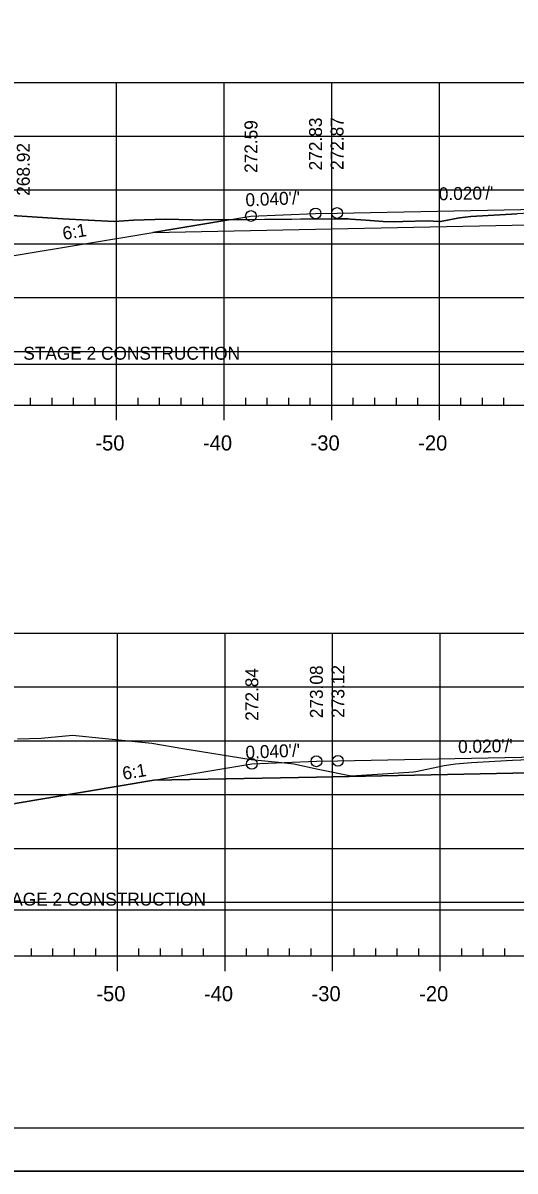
# Model space of a CAD drawing. Extents: x 1365647 to 1367999, y 387113 to 400173.
# Drawn here: x 1365836.1 to 1365881.8, y 388866.1 to 388972.8 of the extents above; entities that cross this region are included whole.
import ezdxf

# ---------------------------------------------------------------- set-up
doc = ezdxf.new("R2010")
doc.units = 0
for name, color, linetype in [('R_Alt Surface', 7, 'Continuous'), ('R_Axis', 7, 'Continuous'), ('R_Axis Annot', 7, 'Continuous'), ('R_Border', 7, 'Continuous'), ('R_Contours', 7, 'Continuous'), ('R_Exist Surface', 7, 'Continuous'), ('R_Fin Surface', 7, 'Continuous'), ('R_Fin Surface Annot', 7, 'Continuous'), ('R_Grid', 7, 'Continuous'), ('R_No Plot', 7, 'Continuous'), ('R_Water', 7, 'Continuous')]:
    doc.layers.add(name, color=color, linetype=linetype)

msp = doc.modelspace()

# ---------------------------------------------------------------- linework, layer by layer
at = {"layer": 'R_Alt Surface'}
for points in [[(1365848.18, 388953.31), (1365863.3, 388953.61), (1365883.08, 388954.01), (1365883.08, 388955.3), (1365894.8, 388955.53), (1365906.8, 388955.29), (1365906.8, 388954), (1365926.3, 388953.61), (1365941.43, 388953.31)], [(1365848.26, 388902.41), (1365863.38, 388902.71), (1365883.15, 388903.1), (1365883.15, 388904.39), (1365894.88, 388904.63), (1365906.85, 388904.39), (1365906.85, 388903.1), (1365926.38, 388902.71), (1365941.51, 388902.41)]]:
    msp.add_lwpolyline(points, dxfattribs=at)
at = {"layer": 'R_Axis'}
for p, q in [((1365836.81, 388937.25), (1365836.81, 388937.95)), ((1365838.81, 388937.25), (1365838.81, 388937.95)), ((1365840.81, 388937.25), (1365840.81, 388937.95)), ((1365842.81, 388937.25), (1365842.81, 388937.95)), ((1365846.81, 388937.25), (1365846.81, 388937.95)), ((1365848.81, 388937.25), (1365848.81, 388937.95)), ((1365850.81, 388937.25), (1365850.81, 388937.95)), ((1365852.81, 388937.25), (1365852.81, 388937.95)), ((1365856.81, 388937.25), (1365856.81, 388937.95)), ((1365858.81, 388937.25), (1365858.81, 388937.95)), ((1365860.81, 388937.25), (1365860.81, 388937.95)), ((1365862.81, 388937.25), (1365862.81, 388937.95)), ((1365866.81, 388937.25), (1365866.81, 388937.95)), ((1365868.81, 388937.25), (1365868.81, 388937.95)), ((1365870.81, 388937.25), (1365870.81, 388937.95)), ((1365872.81, 388937.25), (1365872.81, 388937.95)), ((1365876.81, 388937.25), (1365876.81, 388937.95)), ((1365878.81, 388937.25), (1365878.81, 388937.95)), ((1365880.81, 388937.25), (1365880.81, 388937.95)), ((1365749.81, 388937.25), (1366039.81, 388937.25)), ((1365844.81, 388935.85), (1365844.81, 388937.25)), ((1365854.81, 388935.85), (1365854.81, 388937.25)), ((1365864.81, 388935.85), (1365864.81, 388937.25)), ((1365874.81, 388935.85), (1365874.81, 388937.25)), ((1365836.89, 388886.08), (1365836.89, 388886.78)), ((1365838.89, 388886.08), (1365838.89, 388886.78)), ((1365840.89, 388886.08), (1365840.89, 388886.78)), ((1365842.89, 388886.08), (1365842.89, 388886.78)), ((1365846.89, 388886.08), (1365846.89, 388886.78)), ((1365848.89, 388886.08), (1365848.89, 388886.78)), ((1365850.89, 388886.08), (1365850.89, 388886.78)), ((1365852.89, 388886.08), (1365852.89, 388886.78)), ((1365856.89, 388886.08), (1365856.89, 388886.78)), ((1365858.89, 388886.08), (1365858.89, 388886.78)), ((1365860.89, 388886.08), (1365860.89, 388886.78)), ((1365862.89, 388886.08), (1365862.89, 388886.78)), ((1365866.89, 388886.08), (1365866.89, 388886.78)), ((1365868.89, 388886.08), (1365868.89, 388886.78)), ((1365870.89, 388886.08), (1365870.89, 388886.78)), ((1365872.89, 388886.08), (1365872.89, 388886.78)), ((1365876.89, 388886.08), (1365876.89, 388886.78)), ((1365878.89, 388886.08), (1365878.89, 388886.78)), ((1365880.89, 388886.08), (1365880.89, 388886.78)), ((1365749.89, 388886.08), (1366039.89, 388886.08)), ((1365844.89, 388884.68), (1365844.89, 388886.08)), ((1365854.89, 388884.68), (1365854.89, 388886.08)), ((1365864.89, 388884.68), (1365864.89, 388886.08)), ((1365874.89, 388884.68), (1365874.89, 388886.08))]:
    msp.add_line(p, q, dxfattribs=at)
at = {"layer": 'R_Border'}
msp.add_line((1366052.27, 388870.08), (1365736.09, 388870.08), dxfattribs=at)
at = {"layer": 'R_Contours'}
for p, q in [((1365855.24, 388954.49), (1365848.18, 388953.31)), ((1365855.24, 388954.49), (1365852.9, 388954.47)), ((1365848.18, 388953.31), (1365848.18, 388953.31))]:
    msp.add_line(p, q, dxfattribs=at)
for points in [[(1365852.9, 388954.47), (1365852.56, 388954.44), (1365851.87, 388954.47), (1365849.37, 388954.54), (1365846.37, 388954.44), (1365844.58, 388954.32), (1365839.8, 388954.58), (1365832.2, 388955.07), (1365821.52, 388954.91), (1365820.18, 388954.83), (1365817.33, 388954.91), (1365815.78, 388954.56), (1365815.29, 388954.55), (1365810.51, 388954.54)], [(1365848.18, 388953.31), (1365863.3, 388953.61), (1365883.08, 388954.01), (1365883.08, 388955.11)], [(1365883.08, 388955.11), (1365882.04, 388955.05), (1365877.74, 388954.79), (1365876.69, 388954.66), (1365874.91, 388954.31), (1365874.72, 388954.31), (1365873.74, 388954.38), (1365871.4, 388954.31), (1365870.66, 388954.28), (1365869.59, 388954.31), (1365867.97, 388954.44), (1365866.54, 388954.55), (1365866.34, 388954.56), (1365865.22, 388954.56), (1365855.24, 388954.49)], [(1365810.51, 388954.54), (1365827.97, 388948.72), (1365827.97, 388948.72), (1365835.3, 388951.17), (1365848.17, 388953.31), (1365848.18, 388953.31), (1365848.18, 388953.31), (1365855.24, 388954.49)], [(1365835.61, 388906.25), (1365837.8, 388906.31), (1365840.71, 388906.6), (1365846.86, 388905.99), (1365848.08, 388905.84), (1365850.96, 388905.37), (1365857.31, 388904.34), (1365860.17, 388904.05), (1365861.28, 388903.94), (1365863.53, 388903.44), (1365866.6, 388902.82), (1365871.97, 388903.15), (1365872.4, 388903.18), (1365872.61, 388903.22), (1365875.25, 388903.79), (1365876.31, 388903.93), (1365877.81, 388904.07), (1365881.6, 388904.28), (1365883.15, 388904.34), (1365883.15, 388903.1), (1365863.38, 388902.71), (1365848.26, 388902.41), (1365835.38, 388900.26)]]:
    msp.add_lwpolyline(points, dxfattribs=at)
at = {"layer": 'R_Exist Surface'}
for points in [[(1365832.2, 388955.07), (1365839.8, 388954.58), (1365844.58, 388954.32), (1365846.37, 388954.44), (1365849.37, 388954.54), (1365851.87, 388954.47), (1365852.56, 388954.44), (1365852.9, 388954.47), (1365865.22, 388954.56), (1365866.34, 388954.56), (1365866.54, 388954.55), (1365867.97, 388954.44), (1365869.59, 388954.31), (1365870.66, 388954.28), (1365871.4, 388954.31), (1365873.74, 388954.38), (1365874.72, 388954.31), (1365874.91, 388954.31), (1365876.69, 388954.66), (1365877.74, 388954.79), (1365882.04, 388955.05)], [(1365835.61, 388906.25), (1365837.8, 388906.31), (1365840.71, 388906.6), (1365846.86, 388905.99), (1365848.08, 388905.84), (1365850.96, 388905.37), (1365857.31, 388904.34), (1365860.17, 388904.05), (1365861.28, 388903.94), (1365863.53, 388903.44), (1365866.6, 388902.82), (1365871.97, 388903.15), (1365872.4, 388903.18), (1365872.61, 388903.22), (1365875.25, 388903.79), (1365876.31, 388903.93), (1365877.81, 388904.07), (1365881.6, 388904.28), (1365883.15, 388904.34)]]:
    msp.add_lwpolyline(points, dxfattribs=at)
at = {"layer": 'R_Fin Surface'}
for points in [[(1365810.51, 388954.54), (1365827.97, 388948.72), (1365827.97, 388948.72), (1365835.3, 388951.17), (1365848.17, 388953.31), (1365848.18, 388953.31), (1365848.18, 388953.31), (1365857.3, 388954.83), (1365863.3, 388955.07), (1365865.3, 388955.11), (1365865.31, 388955.11), (1365894.8, 388955.7), (1365894.81, 388955.7), (1365924.3, 388955.11), (1365926.3, 388955.07), (1365932.3, 388954.83), (1365932.3, 388954.83), (1365941.43, 388953.31), (1365941.43, 388953.31), (1365954.3, 388951.17), (1365954.3, 388951.17), (1365969.97, 388956.39)], [(1365804.83, 388906.43), (1365829.36, 388898.25), (1365835.38, 388900.26), (1365848.26, 388902.41), (1365857.38, 388903.93), (1365863.38, 388904.17), (1365865.38, 388904.21), (1365894.88, 388904.8), (1365924.38, 388904.21), (1365926.38, 388904.17), (1365932.38, 388903.93), (1365941.51, 388902.41), (1365954.38, 388900.26), (1365982.22, 388909.54)], [(1365857.38, 388903.93), (1365863.38, 388904.17), (1365865.38, 388904.21), (1365894.88, 388904.8), (1365924.38, 388904.21), (1365926.38, 388904.17), (1365932.38, 388903.93)]]:
    msp.add_lwpolyline(points, dxfattribs=at)
at = {"layer": 'R_Grid'}
for p, q in [((1365749.81, 388967.25), (1366039.81, 388967.25)), ((1365844.81, 388937.25), (1365844.81, 388967.25)), ((1365854.81, 388937.25), (1365854.81, 388967.25)), ((1365864.81, 388937.25), (1365864.81, 388967.25)), ((1365874.81, 388937.25), (1365874.81, 388967.25)), ((1365749.81, 388962.25), (1366039.81, 388962.25)), ((1365749.81, 388957.25), (1366039.81, 388957.25)), ((1365749.81, 388952.25), (1366039.81, 388952.25)), ((1365749.81, 388947.25), (1366039.81, 388947.25)), ((1365749.81, 388942.25), (1366039.81, 388942.25)), ((1365749.81, 388937.25), (1366039.81, 388937.25)), ((1365749.89, 388916.08), (1366039.89, 388916.08)), ((1365844.89, 388886.08), (1365844.89, 388916.08)), ((1365854.89, 388886.08), (1365854.89, 388916.08)), ((1365864.89, 388886.08), (1365864.89, 388916.08)), ((1365874.89, 388886.08), (1365874.89, 388916.08)), ((1365749.89, 388911.08), (1366039.89, 388911.08)), ((1365749.89, 388906.08), (1366039.89, 388906.08)), ((1365749.89, 388901.08), (1366039.89, 388901.08)), ((1365749.89, 388896.08), (1366039.89, 388896.08)), ((1365749.89, 388891.08), (1366039.89, 388891.08)), ((1365749.89, 388886.08), (1366039.89, 388886.08))]:
    msp.add_line(p, q, dxfattribs=at)
at = {"layer": 'R_No Plot'}
msp.add_line((1365723.69, 388866.1), (1366057.03, 388866.1), dxfattribs=at)
msp.add_lwpolyline([(1365723.69, 389079.44), (1366057.03, 389079.44), (1366057.03, 388866.1), (1365723.69, 388866.1)], close=True, dxfattribs=at)
for centre in [(1365857.3, 388954.83), (1365863.3, 388955.07), (1365865.3, 388955.11), (1365857.38, 388903.93), (1365857.38, 388903.93), (1365857.38, 388903.93), (1365857.38, 388903.93), (1365857.38, 388903.93), (1365863.38, 388904.17), (1365863.38, 388904.17), (1365863.38, 388904.17), (1365863.38, 388904.17), (1365863.38, 388904.17), (1365865.38, 388904.21), (1365865.38, 388904.21), (1365865.38, 388904.21), (1365865.38, 388904.21), (1365865.38, 388904.21)]:
    msp.add_circle(centre, 0.5, dxfattribs=at)
at = {"layer": 'R_Water'}
for p, q in [((1365810.51, 388941.08), (1365883.08, 388941.08)), ((1365804.83, 388890.37), (1365883.15, 388890.37))]:
    msp.add_line(p, q, dxfattribs=at)

# ---------------------------------------------------------------- texts
at = {"layer": 'R_Axis Annot'}
for s, p in [('-50', (1365842.84, 388933.05)), ('-40', (1365852.84, 388933.05)), ('-30', (1365862.84, 388933.05)), ('-20', (1365872.84, 388933.05)), ('-50', (1365842.93, 388881.88)), ('-40', (1365852.93, 388881.88)), ('-30', (1365862.93, 388881.88)), ('-20', (1365872.93, 388881.88))]:
    msp.add_text(s, height=1.4, dxfattribs=at).set_placement(p)
at = {"layer": 'R_Fin Surface Annot'}
for s, rotation, p in [('272.59', 90, (1365857.9, 388958.83)), ('272.83', 90, (1365863.9, 388959.07)), ('272.87', 90, (1365865.9, 388959.11)), ('268.92', 90, (1365836.74, 388956.71)), ("0.040'/'", 2.2906, (1365856.81, 388955.73)), ("0.020'/'", 1.1458, (1365874.77, 388956.29)), ('6:1', 9.4623, (1365839.89, 388952.61)), ('272.84', 90, (1365857.98, 388907.93)), ('272.84', 90, (1365857.98, 388907.93)), ('272.84', 90, (1365857.98, 388907.93)), ('273.08', 90, (1365863.98, 388908.17)), ('273.08', 90, (1365863.98, 388908.17)), ('273.08', 90, (1365863.98, 388908.17)), ('273.12', 90, (1365865.98, 388908.21)), ('273.12', 90, (1365865.98, 388908.21)), ('273.12', 90, (1365865.98, 388908.21)), ("0.020'/'", 1.1458, (1365876.56, 388904.93)), ("0.040'/'", 2.2906, (1365856.81, 388904.4)), ('6:1', 9.4623, (1365845.45, 388902.44))]:
    msp.add_text(s, height=1.2, rotation=rotation, dxfattribs=at).set_placement(p)
at = {"layer": 'R_Water'}
for p in [(1365836.14, 388941.48), (1365832.97, 388890.76)]:
    msp.add_text('STAGE 2 CONSTRUCTION', height=1.2, dxfattribs=at).set_placement(p)

doc.saveas('drawing.dxf')
